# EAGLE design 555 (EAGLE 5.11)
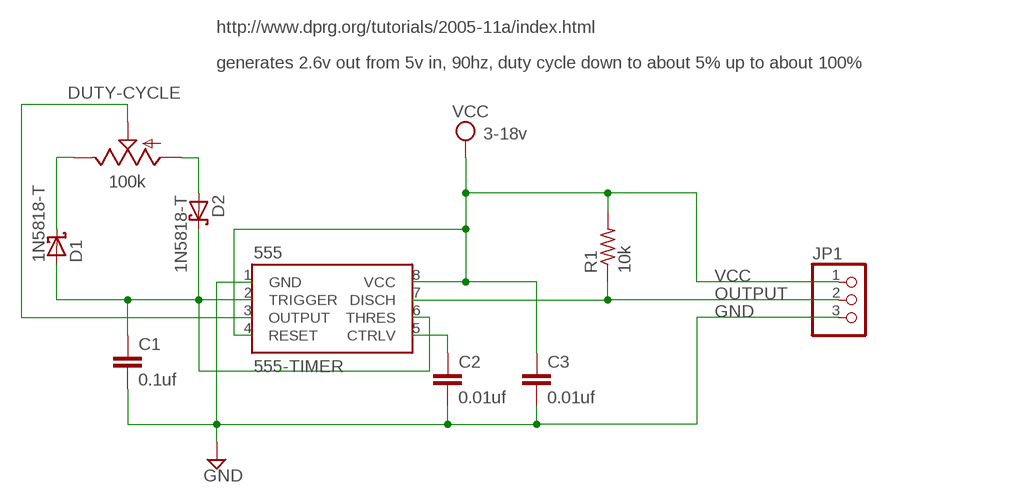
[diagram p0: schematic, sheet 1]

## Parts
555  555-TIMER  [8DIP]
C1  0.1uf  C-EU050-024X044  [C050-024X044]
C2  0.01uf  C-EU050-024X044  [C050-024X044]
C3  0.01uf  C-EU050-024X044  [C050-024X044]
D1  1N5818-T  [DO41-7.6]
D2  1N5818-T  [DO41-7.6]
DUTY-CYCLE  100k  POT-TRIM-3.5IN  [POT-TRIM-3.5IN]
JP1  PINHD-1X3  [1X03]
R1  10k  R-US_0207/10  [0207/10]

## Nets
GND: 555.1(GND) C1.2 C2.2 C3.2 JP1.3
N$1: 555.2(TRIGGER) 555.6(THRES) C1.1 D1.A D2.C
N$2: D1.C DUTY-CYCLE.3(E)
N$3: D2.A DUTY-CYCLE.1(A)
N$4: 555.3(OUTPUT) DUTY-CYCLE.2(S)
N$5: 555.5(CTRLV) C2.1
OUTPUT: 555.7(DISCH) JP1.2 R1.1
VCC: 555.4(RESET) 555.8(VCC) C3.1 JP1.1 R1.2

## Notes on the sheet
- http://www.dprg.org/tutorials/2005-11a/index.html
- generates 2.6v out from 5v in, 90hz, duty cycle down to about 5% up to about 100%
- 3-18v

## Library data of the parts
555 = trl:555-TIMER
C1-C3 = rcl:C-EU: CAPACITOR, European symbol
D1 D2 = diode:1N581*: 1.0A SCHOTTKY BARRIER RECTIFIER
DUTY-CYCLE = trl:POT-TRIM-3.5IN
JP1 = pinhead:PINHD-1X3: PIN HEADER
R1 = resistor:R-US_: RESISTOR, American symbol

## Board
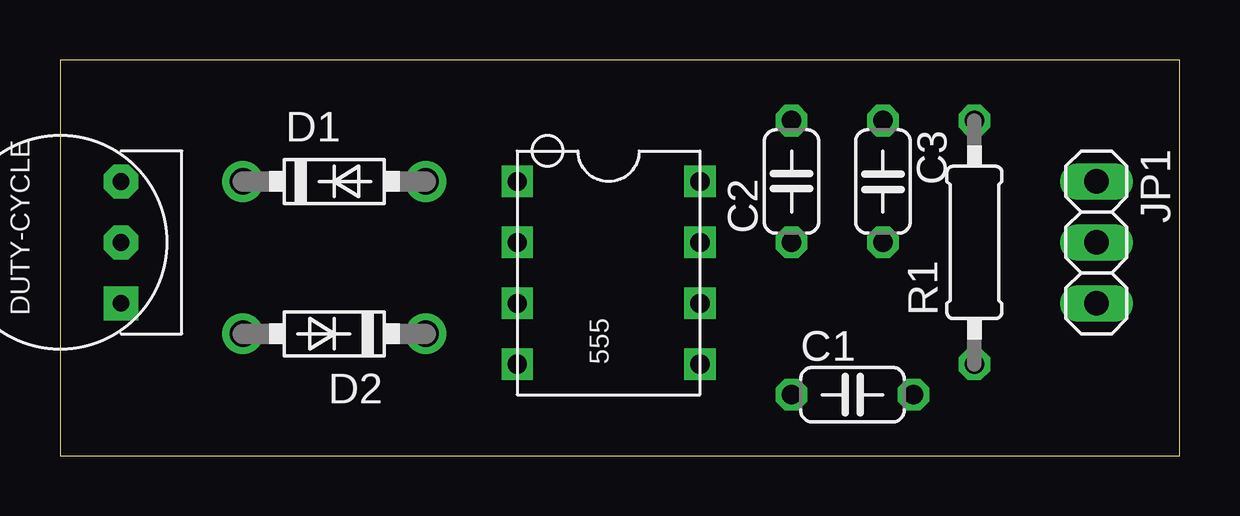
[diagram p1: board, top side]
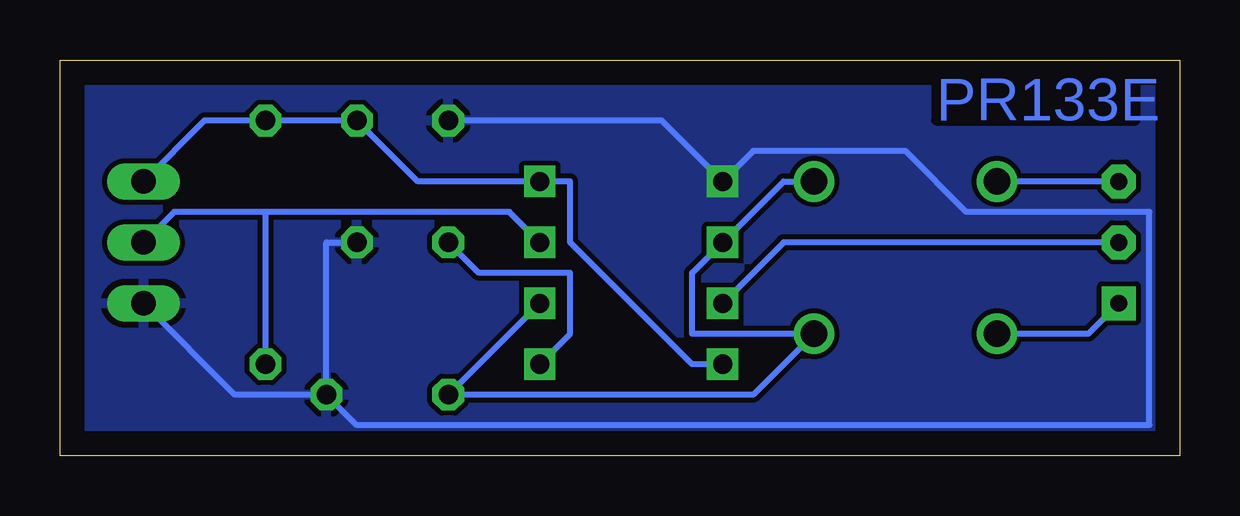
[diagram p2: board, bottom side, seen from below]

Size 46.66 x 16.5 mm. Coordinates in mm from the lower left corner, seen from the top.
Outline: 0,0 46.66,0 46.66,16.5 0,16.5 0,0
Copper layers (1*16): Top 0.035mm / dielectric 1.5mm / Bottom 0.035mm
Design rules "default": minimum track width 10mil, minimum drill 24mil, track to track 8mil, track to pad 8mil, pad to pad 8mil, via to via 8mil, smd to smd 8mil, copper to edge 40mil, drill to drill 8mil, minimum pad ring 10mil, minimum via ring 8mil, stop-mask expansion 4mil, vias tented up to drill 0mil, thermal gap 10mil

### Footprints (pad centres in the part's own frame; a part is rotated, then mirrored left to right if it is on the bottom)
8DIP = drill 0.8 square: 1 -3.81,3.81; 2 -3.81,1.27; 3 -3.81,-1.27; 4 -3.81,-3.81; 5 3.81,-3.81; 6 3.81,-1.27; 7 3.81,1.27; 8 3.81,3.81
C050-024X044 = drill 0.813 octagon: 1 -2.54,0; 2 2.54,0
DO41-7.6 = drill 1.1 pad 1.7 round: A 3.81,0; C -3.81,0
POT-TRIM-3.5IN = drill 0.7 pad 1.422 square: 1 -2.54,-3.81 | drill 0.7 pad 1.422 octagon: 2 0,-3.81; 3 2.54,-3.81
1X03 = drill 1.016 long: 1 -2.54,0; 2 0,0; 3 2.54,0
0207/10 = drill 0.813 octagon: 1 -5.08,0; 2 5.08,0

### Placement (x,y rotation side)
555  22.86,7.62 0 top
C1  33.02,2.54 0 top
C2  30.48,11.43 90 top
C3  34.29,11.43 270 top
D1  11.43,11.43 0 top
D2  11.43,5.08 180 top
DUTY-CYCLE  -1.27,8.89 90 top
JP1  43.18,8.89 270 top
R1  38.1,8.89 90 top

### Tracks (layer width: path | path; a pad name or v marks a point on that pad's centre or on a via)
GND
  Bottom 0.254: C2.2 21.59,13.97 555.1 17.78,12.7 11.43,12.7 8.89,10.16 1.27,10.16 1.27,1.27 34.29,1.27 C1.2 | C1.2 35.56,8.89 C3.2 | JP1.3 39.37,2.54 C1.2
  pour Bottom: 0,16.51 46.99,16.51 46.99,0 0,0 0,1.27
N$1
  Bottom 0.254: D1.A 16.51,11.43 555.2 20.32,7.62 20.32,5.08 D2.C 17.78,2.54 C1.1 555.6
N$2
  Bottom 0.254: DUTY-CYCLE.3 D1.C
N$3
  Bottom 0.254: DUTY-CYCLE.1 3.81,5.08 D2.A
N$4
  Bottom 0.254: 555.3 16.51,8.89 DUTY-CYCLE.2
N$5
  Bottom 0.254: 555.5 25.4,5.08 25.4,7.62 29.21,7.62 C2.1
OUTPUT
  Bottom 0.254: 555.7 27.94,10.16 38.1,10.16 | 38.1,10.16 41.91,10.16 JP1.2 | 38.1,10.16 R1.1
VCC
  Bottom 0.254: JP1.1 40.64,13.97 R1.2 C3.1 31.75,11.43 555.8 25.4,11.43 25.4,8.89 20.32,3.81 555.4

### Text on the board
Bottom: PR133E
